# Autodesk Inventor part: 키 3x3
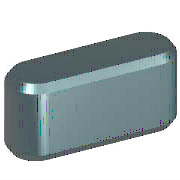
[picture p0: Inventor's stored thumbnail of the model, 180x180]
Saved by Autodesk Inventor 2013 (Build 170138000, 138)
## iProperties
Created: 2012-02
Part Number: 키 3x3
Material: 강철, 연강
Description: 키 및 해당 키홈
Document SubType Name: Modeling
Standard: KS B 1311
Designer: mduedu
Standards Organization: KS
Language: ko-KR
Size Designation: 3 x 3 x 12
Categories: <MemberInstance><Categories><Category DisplayName="샤프트 부품" InternalName="7f7aeb1f-a693-4053-b835-cee3144e0d98" Mnemonic="SHFT"><Category DisplayName="키" Interna
Density: 7.86 g/cm^3
Mass: 0.790122 g
Surface Area: 1.42216 cm^2
Volume: 0.100524 cm^3
IsCustomPart: 1
Author: mduedu
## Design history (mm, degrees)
workplane "Work Plane1"
workplane "Work Plane2"
sketch "스케치1"
  geometry: L1 (1.5, 1.5)-(10.5, 1.5); L2 (10.5, -1.5)-(1.5, -1.5); L3 (0, 9.4)-(0, -7.4) reference; L4 (-5, 0)-(30, 0) reference; L5 (12, 0)-(12, 7); A1 r 1.5 centre (1.5, 0) between (1.5, 1.5) and (1.5, -1.5); A2 r 1.5 centre (10.5, 0) between (10.5, -1.5) and (10.5, 1.5)
  constraints: 6 end point, 5 point on circle, 4 tangent, 3 point on line, 2 centre point, 1 horizontal, 1 parallel, 1 perpendicular
  dimensions: "d0" = 1.5 radius of A1 (= 0.5 x PB); "d13" = 1.5 radius of A2 (= 0.5 x PB); "d14" = 12 distance between parallel lines of L5 L3 (= NLG)
extrude "본체1" new body sketch "스케치1" taper "d3" = 0 deg; stored distance "d4" = 10
workplane "Work Plane3"
body "Solid1"
chamfer "모따기1" distance "d8" = 0.25 (= PHH); stored, may be unused: second distance "d9" = 0.25 (= PHH), angle "d15" = 45 deg
other parameters: "d1" = -1.8 (= -PNT), "d2" = 1.2 (= PH - PNT), "NLG" = 12 [user parameter; used in 3 equation terms], "PB" = 3 [user parameter; used in 2 equation terms], "PNT" = 1.8 [user parameter; used in 2 equation terms], "PH" = 3 [user parameter; used in 1 equation term], "PHH" = 0.25 [user parameter; used in 2 equation terms], "d10" = 0, "d16" = 0, "d17" = 0, "d18" = 0, "WDMIN" = 8 [user parameter], "PLB2" = 12 (= NLG) [user parameter], "PLB1" = 12 (= NLG) [user parameter], "RR" = 0.08 [user parameter], "PUEB" = 1.4 [user parameter]
